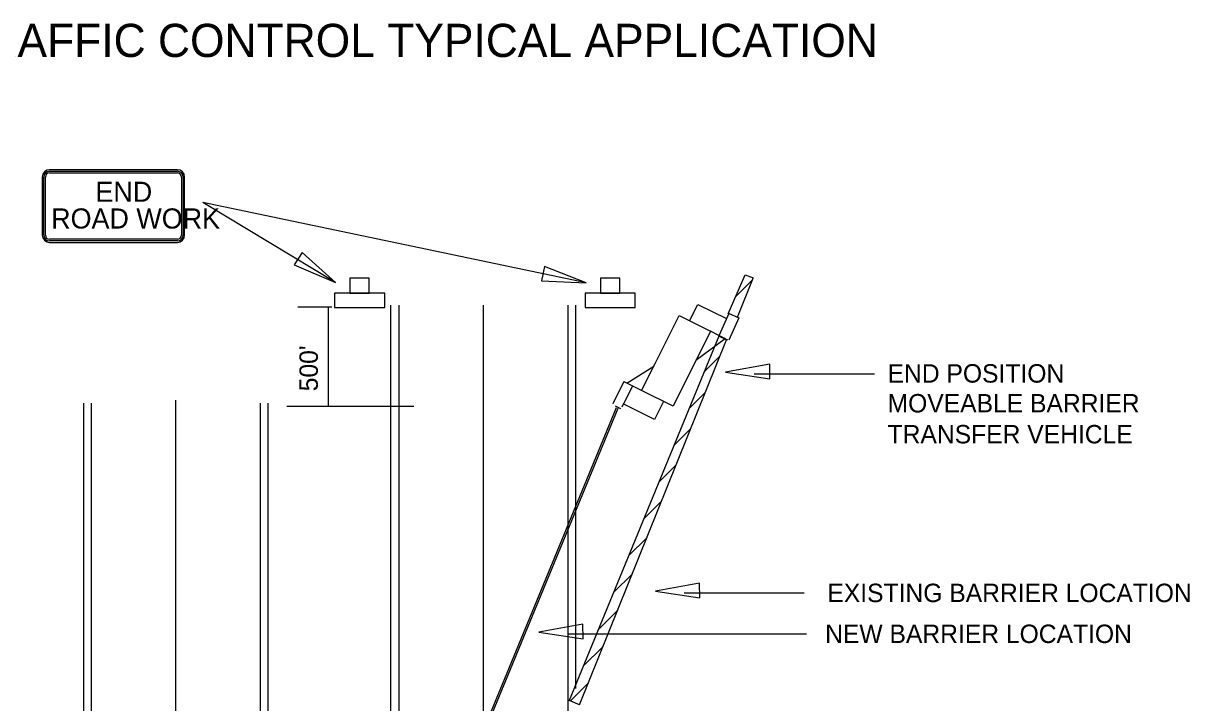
# Model space of a CAD drawing. Extents: x 54531.5 to 54538.4, y 53883.4 to 53893.4.
# Drawn here: x 54533.856 to 54537.652, y 53891.237 to 53893.449 of the extents above; entities that cross this region are included whole.
import ezdxf

# ---------------------------------------------------------------- set-up
doc = ezdxf.new("R2010")
doc.units = 0
for name, color, linetype in [('DETL-DIMS', 7, 'Continuous'), ('DETL-LINE', 7, 'Continuous'), ('DETL-NOTE', 7, 'Continuous'), ('DETL-TITL', 7, 'Continuous')]:
    doc.layers.add(name, color=color, linetype=linetype)

msp = doc.modelspace()

# ---------------------------------------------------------------- linework, layer by layer
at = {"layer": 'DETL-DIMS'}
for p, q in [((54534.8718, 53892.6052), (54534.4396, 53892.865)), ((54535.6876, 53892.6037), (54534.4396, 53892.865)), ((54534.7494, 53892.5253), (54534.8595, 53892.5253)), ((54534.8492, 53892.2021), (54534.8492, 53892.5253)), ((54536.2349, 53892.3074), (54536.6257, 53892.3074)), ((54534.7133, 53892.2021), (54535.1263, 53892.2021)), ((54536.0068, 53891.5944), (54536.3976, 53891.5944)), ((54535.6268, 53891.4612), (54536.4053, 53891.4612))]:
    msp.add_line(p, q, dxfattribs=at)
for points in [[(54534.7631, 53892.7025), (54534.7373, 53892.662), (54534.8718, 53892.6052)], [(54535.5519, 53892.6573), (54535.5418, 53892.6104), (54535.6876, 53892.6037)], [(54536.2858, 53892.2908), (54536.2851, 53892.3388), (54536.1414, 53892.3128)], [(54536.0577, 53891.5778), (54536.057, 53891.6258), (54535.9134, 53891.5997)], [(54535.6776, 53891.4447), (54535.677, 53891.4927), (54535.5333, 53891.4666)]]:
    msp.add_lwpolyline(points, close=True, dxfattribs=at)
at = {"layer": 'DETL-LINE'}
for p, q in [((54534.3569, 53892.9719), (54533.9409, 53892.9719)), ((54533.9409, 53892.9671), (54534.3569, 53892.9671)), ((54533.9409, 53892.9621), (54534.3569, 53892.9621)), ((54533.9174, 53892.9484), (54533.9174, 53892.7592)), ((54533.9222, 53892.7592), (54533.9222, 53892.9484)), ((54533.9272, 53892.7592), (54533.9272, 53892.9484)), ((54534.3704, 53892.9484), (54534.3704, 53892.7592)), ((54534.3705, 53892.9482), (54534.3704, 53892.9484)), ((54534.3759, 53892.9484), (54534.3759, 53892.7592)), ((54534.3807, 53892.7592), (54534.3807, 53892.9484)), ((54534.3569, 53892.7457), (54533.9409, 53892.7457)), ((54534.3569, 53892.7403), (54533.9409, 53892.7403)), ((54533.9409, 53892.7355), (54534.3569, 53892.7355)), ((54536.1503, 53892.5027), (54536.205, 53892.6304)), ((54536.1801, 53892.4921), (54536.2315, 53892.6192)), ((54536.205, 53892.6304), (54536.2317, 53892.6197)), ((54536.2315, 53892.6192), (54536.2317, 53892.6197)), ((54536.1742, 53892.5584), (54536.2291, 53892.6135)), ((54535.0519, 53889.8808), (54535.0519, 53892.5314)), ((54535.0775, 53892.5314), (54535.0775, 53890.1332)), ((54535.3526, 53892.5314), (54535.3526, 53885.9139)), ((54535.6275, 53892.5314), (54535.6275, 53889.7593)), ((54535.6526, 53892.5314), (54535.6526, 53891.2828)), ((54536.0244, 53892.4801), (54536.0513, 53892.5338)), ((54536.0513, 53892.5338), (54536.1443, 53892.4872)), ((54536.1518, 53892.5044), (54536.121, 53892.434)), ((54536.1508, 53892.5049), (54536.1847, 53892.4904)), ((54535.9122, 53892.3411), (54535.9903, 53892.4972)), ((54535.9903, 53892.4972), (54536.0927, 53892.446)), ((54536.1845, 53892.4904), (54536.1524, 53892.4172)), ((54536.1791, 53892.4928), (54536.1811, 53892.4948)), ((54536.1192, 53892.4304), (54535.6323, 53891.2437)), ((54536.0927, 53892.446), (54535.9707, 53892.202)), ((54536.1491, 53892.4176), (54536.0926, 53892.446)), ((54536.1443, 53892.418), (54536.1192, 53892.4304)), ((54536.1412, 53892.4216), (54536.1239, 53892.4303)), ((54535.6664, 53891.2297), (54536.1443, 53892.418)), ((54536.1403, 53892.4214), (54536.045, 53892.3506)), ((54536.0717, 53892.3146), (54536.1235, 53892.3664)), ((54535.8197, 53892.2776), (54535.9077, 53892.3321)), ((54535.8683, 53892.2532), (54535.9122, 53892.3411)), ((54535.9122, 53892.3411), (54535.9122, 53892.3411)), ((54535.8107, 53892.2828), (54535.774, 53892.2096)), ((54535.8103, 53892.2822), (54535.8862, 53892.2443)), ((54535.8389, 53892.2682), (54535.8101, 53892.2108)), ((54535.9707, 53892.202), (54535.8683, 53892.2532)), ((54536.0225, 53892.1947), (54536.0759, 53892.2481)), ((54534.0519, 53892.2124), (54534.0519, 53885.9452)), ((54534.0768, 53892.2124), (54534.0768, 53885.9452)), ((54534.3519, 53885.8441), (54534.3519, 53892.2214)), ((54534.6268, 53892.2124), (54534.6268, 53885.9452)), ((54534.6519, 53892.2124), (54534.6519, 53885.9452)), ((54535.3648, 53891.1732), (54535.7863, 53892.1976)), ((54535.3699, 53891.1719), (54535.7914, 53892.1963)), ((54535.7825, 53892.2032), (54535.7998, 53892.1945)), ((54535.8048, 53892.1998), (54535.8095, 53892.2094)), ((54535.9106, 53892.1589), (54535.8077, 53892.2104)), ((54535.9399, 53892.2175), (54535.9106, 53892.1589)), ((54535.9733, 53892.0748), (54536.0284, 53892.1299)), ((54535.9241, 53891.9548), (54535.9808, 53892.0116)), ((54535.8749, 53891.835), (54535.9333, 53891.8933)), ((54535.8257, 53891.7151), (54535.8857, 53891.7751)), ((54535.7766, 53891.5952), (54535.8382, 53891.6568)), ((54535.7274, 53891.4752), (54535.7906, 53891.5385)), ((54535.6782, 53891.3554), (54535.7431, 53891.4203)), ((54535.6358, 53891.2423), (54535.6955, 53891.302)), ((54535.6664, 53891.2297), (54535.6323, 53891.2437))]:
    msp.add_line(p, q, dxfattribs=at)
for points in [[(54534.9818, 53892.6193), (54534.9188, 53892.6193), (54534.9188, 53892.5706), (54534.9818, 53892.5706)], [(54535.7972, 53892.6193), (54535.7342, 53892.6193), (54535.7342, 53892.5706), (54535.7972, 53892.5706)], [(54534.8685, 53892.5706), (54534.8685, 53892.5236), (54535.032, 53892.5236), (54535.032, 53892.5706)], [(54535.6839, 53892.5706), (54535.6839, 53892.5236), (54535.8474, 53892.5236), (54535.8474, 53892.5706)]]:
    msp.add_lwpolyline(points, close=True, dxfattribs=at)
for points in [[(54535.3526, 53892.3514), (54535.3526, 53892.2314)], [(54534.3519, 53891.7841), (54534.3519, 53891.9041)], [(54535.3526, 53891.8714), (54535.3526, 53891.7514)], [(54534.3519, 53891.3041), (54534.3519, 53891.4241)], [(54535.3526, 53891.3914), (54535.3526, 53891.2714)]]:
    msp.add_lwpolyline(points, dxfattribs=at)
for centre, radius, start, end in [((54533.9409, 53892.9483), 0.0237, 90, 180), ((54533.9409, 53892.9483), 0.0189, 90, 180), ((54533.9409, 53892.9483), 0.0136, 90, 180), ((54534.3569, 53892.9483), 0.0237, 0, 90), ((54534.3569, 53892.9483), 0.0189, 0, 90), ((54534.3569, 53892.9483), 0.0136, 0, 90), ((54533.9409, 53892.7592), 0.0237, 180, 270), ((54533.9409, 53892.7592), 0.0189, 180, 270), ((54533.9409, 53892.7592), 0.0136, 180, 270), ((54534.3569, 53892.7592), 0.0237, 270, 0), ((54534.3569, 53892.7592), 0.0136, 270, 0), ((54534.3569, 53892.7592), 0.0189, 270, 0)]:
    msp.add_arc(centre, radius, start, end, dxfattribs=at)

# ---------------------------------------------------------------- texts
for s, p in [('END', (54534.0902, 53892.8676)), ('ROAD WORK', (54533.9462, 53892.7806))]:
    msp.add_text(s, height=0.06548, rotation=360, dxfattribs=at).set_placement(p)
at = {"layer": 'DETL-NOTE'}
msp.add_text("500'", height=0.06, rotation=90, dxfattribs=at).set_placement((54534.8143, 53892.2508))
for s, p in [('END POSITION', (54536.6688, 53892.279)), ('MOVEABLE BARRIER', (54536.6688, 53892.1819)), ('TRANSFER VEHICLE', (54536.6688, 53892.0811)), ('EXISTING BARRIER LOCATION', (54536.4728, 53891.5644)), ('NEW BARRIER LOCATION', (54536.4655, 53891.4312))]:
    msp.add_text(s, height=0.06, dxfattribs=at).set_placement(p)
at = {"layer": 'DETL-TITL'}
msp.add_text('TEMPORARY TRAFFIC CONTROL TYPICAL APPLICATION', height=0.108, dxfattribs=at).set_placement((54532.6891, 53893.3391))

doc.saveas('drawing.dxf')
